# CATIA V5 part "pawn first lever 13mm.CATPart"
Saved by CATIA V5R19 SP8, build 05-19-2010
Part number: pawn first lever 13mm
Bounding box of the stored display mesh (mm): x 146.693 to 165.693, y 69.1 to 107.1, z 33.688 to 52.688
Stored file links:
  G:\EU_thinkMotion\CFAO_2010\MMS_groupe1\MMS_groupe1\A reprendre\gduval\CFAO kinematic ok\pawn first lever 13mm.CATPart
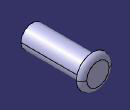
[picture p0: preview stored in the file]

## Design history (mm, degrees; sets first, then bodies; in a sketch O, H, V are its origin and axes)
Body1 (main body)
  Plane1: stored without definition
  Point1: stored without definition
  Sketch1 on Plane1, origin (0, 104.1, 0), H (-1, 0, 0), V (0, 0, 1)
    circle A1 centre (-156.193, 43.188) radius 6.5
    point P1 (-156.193, 43.188)
    reference projected point E1 (-156.193, 43.188) from Point1
    radius A1 = 6.5
    coincidence: P1 E1
  Pad1: profile Sketch1, direction (0, -1, 0), length 35
  Sketch2 on start face of Pad1, origin (0, 104.1, 0), H (-1, 0, 0), V (0, 0, 1)
    circle A1 centre (-156.193, 43.188) radius 9.5
    reference projected circle E1 centre (-156.193, 43.188) radius 6.5 from Sketch1.A1
    radius A1 = 9.5
    concentricity: E1 A1
  Pad2: profile Sketch2, direction (0, 1, 0), length 3
  Fillet1: radius 3, on edge [face of Pad2 from Sketch2.A1 | end face of Pad2]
